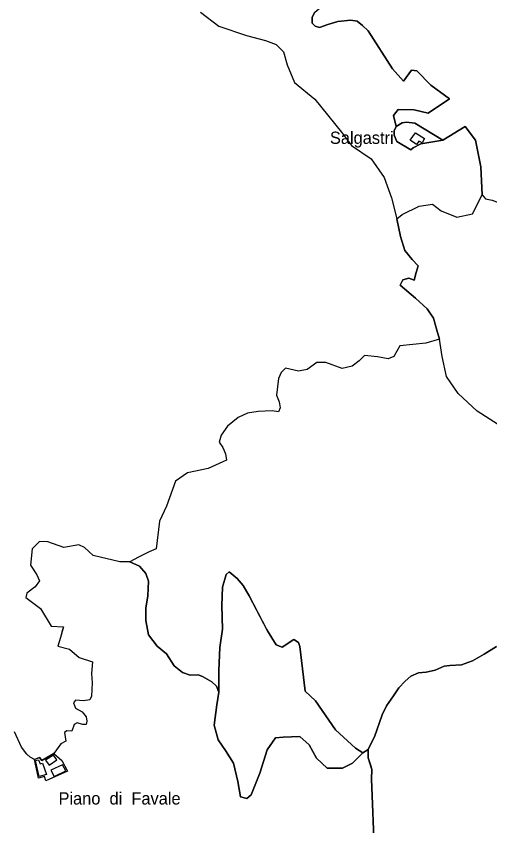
# Model space of a CAD drawing. Extents: x 645880 to 658994, y 884400 to 894744.
# Drawn here: x 655242 to 655899, y 892132 to 893255 of the extents above; entities that cross this region are included whole.
import ezdxf
from ezdxf.enums import TextEntityAlignment as Align

# ---------------------------------------------------------------- set-up
doc = ezdxf.new("R2010")
doc.units = 0
doc.header["$LTSCALE"] = 10
for name, color, linetype, lineweight in [('16', 7, 'Continuous', 25), ('17', 7, 'Continuous', 25), ('18', 7, 'Continuous', 25), ('4', 7, 'Continuous', 25)]:
    doc.layers.add(name, color=color, linetype=linetype, lineweight=lineweight)
doc.layers.add('60', color=7, linetype='Continuous')

msp = doc.modelspace()

# ---------------------------------------------------------------- linework, layer by layer
at = {"layer": '16'}
for points in [[(655652.59, 893245.87), (655652.9, 893254.21), (655656.27, 893260.95), (655673.25, 893274.81), (655677.27, 893286.81), (655672.13, 893296.24), (655662.77, 893302.78), (655661.99, 893309.77), (655670.76, 893325.78), (655674.38, 893335.22), (655673.89, 893349.59), (655656.98, 893368.6), (655634.51, 893389.65), (655626.13, 893385.49), (655607.9, 893382.51), (655593.91, 893399.81), (655585.33, 893424.33), (655583.16, 893438.12), (655583.47, 893454.87), (655594.74, 893465.4)], [(655497.71, 893261.19), (655523.09, 893241.6), (655561.51, 893228.53), (655588.19, 893221.64), (655602.74, 893216.24), (655612.98, 893206.04), (655618.05, 893187.89), (655628.2, 893163.22), (655656.35, 893140.23), (655693.22, 893094.49), (655707.43, 893075.95), (655734.54, 893057.47), (655752.43, 893031.48), (655762.74, 893003.47), (655769.96, 892974.46), (655777.68, 892980.49), (655801.34, 892991.77), (655819.4, 892994.83), (655831.69, 892985.31), (655853.49, 892976.46), (655875.14, 892981.46), (655888.55, 893007.47), (655886.49, 893046.49), (655879.27, 893083.5)], [(655662.77, 893239.64), (655656.86, 893241.52), (655652.59, 893245.87)], [(655730.58, 893235.17), (655722.66, 893242.51), (655714.96, 893248.35), (655706.21, 893249.85), (655688.18, 893248.26), (655674.37, 893243.99), (655662.77, 893239.64)], [(655879.27, 893083.5), (655864.69, 893102.53), (655833.82, 893083.57), (655803.46, 893078.52), (655792.86, 893072.99), (655789.63, 893070.22), (655770.26, 893081.76), (655766.58, 893090.52), (655766.58, 893096.52), (655769.34, 893102.52), (655765.35, 893117.58), (655772.03, 893126.17), (655793.99, 893125.7), (655813.56, 893120.92), (655843.28, 893140.94), (655817.19, 893159.62), (655797.97, 893179.45), (655790.64, 893180.44), (655779.55, 893165.41), (655764.26, 893182.3), (655730.58, 893235.17)], [(655829.33, 892807.49), (655810.29, 892801.7), (655774.43, 892798.33)], [(656246.73, 892704.86), (656219.92, 892710.37), (656199.3, 892713.37), (656162.69, 892717.37), (656141.04, 892717.37), (656125.57, 892716.37), (656121.36, 892719.13), (656121.12, 892718.66), (656104.57, 892695.85), (656075.19, 892664.84), (656044.38, 892632.77), (656026.62, 892616.45), (656007.72, 892614.56), (655991.84, 892616.22), (655982.38, 892619.71), (655921.47, 892682.13), (655881.54, 892707.33), (655855.43, 892732.01), (655839.07, 892755.46), (655833.01, 892783.59), (655829.33, 892807.49)], [(655774.43, 892798.33), (655766.1, 892783.46), (655757.98, 892780.28), (655743.16, 892783.04), (655725.28, 892784.65), (655717.86, 892777.36), (655708.44, 892770.17), (655694.18, 892766.93), (655671.49, 892774.93), (655659.12, 892774.93), (655645.82, 892765.21), (655633.73, 892763.23), (655615.9, 892767)], [(655615.9, 892767), (655609.95, 892761.25), (655605.91, 892752.7), (655603.47, 892729.73), (655607.01, 892720.72)], [(655607.01, 892720.72), (655608.37, 892712.07), (655606.23, 892706.52), (655597.25, 892707.91), (655577.66, 892706.91), (655563.22, 892704.9)], [(655563.22, 892704.9), (655550.3, 892698.78), (655535.38, 892686.9)], [(655535.38, 892686.9), (655526.32, 892674.39), (655523.54, 892664.68)], [(655523.54, 892664.68), (655528.69, 892657.34), (655532.65, 892648.22), (655533.84, 892639.5), (655508.35, 892628.05), (655479.97, 892622), (655463.29, 892610.35), (655450.61, 892575.65), (655441.09, 892554.83), (655436.55, 892516.76), (655426.64, 892512.59), (655411.78, 892505.06), (655399.88, 892498.36)], [(655399.88, 892498.36), (655385.88, 892498.36), (655349.06, 892507.48), (655336.89, 892518.38), (655329.35, 892522.07), (655308.36, 892518.29), (655286.28, 892526.37), (655274.44, 892526.91), (655264.21, 892516.68), (655262.18, 892493.74), (655270.7, 892480.65), (655274.66, 892472.33), (655268.68, 892463.93), (655256.83, 892455.07), (655255.84, 892449.13), (655275.9, 892433.92), (655290.92, 892409.47), (655307.96, 892408.48), (655306.66, 892404.1), (655303.61, 892393.8), (655300.24, 892381.51), (655316.29, 892377.54), (655329.56, 892365.85), (655348.08, 892359.9), (655346.61, 892343.64), (655347.6, 892330.75), (655346.61, 892312.11), (655344.63, 892307.34), (655335.47, 892305.7), (655324.42, 892306.75), (655321.65, 892302.98), (655324.62, 892295.64), (655333.93, 892290.29), (655339.09, 892283.55), (655340.27, 892277.4), (655339.48, 892272.84), (655334.53, 892272.84), (655329.83, 892274.43), (655326.74, 892275.43), (655322.61, 892272.93)], [(655399.88, 892498.36), (655413.34, 892492.44), (655421.95, 892482.2), (655425.72, 892471.97), (655424.65, 892451.49), (655421.95, 892434.26), (655421.95, 892417.02), (655425.66, 892397.27), (655437.8, 892381.55), (655450.65, 892370.83)], [(655421.95, 892417.02), (655421.95, 892434.26), (655424.65, 892451.49), (655425.72, 892471.97), (655421.95, 892482.2), (655413.34, 892492.44), (655399.88, 892498.36)], [(655450.65, 892370.83), (655461.34, 892354.31), (655472.95, 892345.28), (655483.52, 892341.41), (655494.87, 892341.67), (655500.54, 892339.61), (655513.43, 892332.12), (655520.14, 892326.19), (655523.53, 892317.96), (655523.46, 892347.69), (655524.46, 892379.77), (655528.47, 892405.04), (655527.47, 892438.09), (655528.47, 892463.37), (655533.48, 892480.87), (655537.49, 892484.75), (655548.95, 892475.27)], [(655548.95, 892475.27), (655557.13, 892465.95), (655565.32, 892451.26), (655589.56, 892405.18), (655589.56, 892405.17)], [(655520.14, 892326.19), (655513.43, 892332.12), (655500.54, 892339.61), (655494.87, 892341.67), (655483.52, 892341.41), (655472.95, 892345.28), (655461.34, 892354.31), (655450.65, 892370.83), (655437.8, 892381.55), (655425.66, 892397.27), (655421.95, 892417.02)], [(655589.56, 892405.17), (655590.72, 892402.96), (655602.65, 892383.23), (655611.36, 892380.32), (655627.13, 892390.81)], [(655627.13, 892390.81), (655633.75, 892386.84), (655635.64, 892380.99), (655642.99, 892319.23), (655657.33, 892305.63), (655685.32, 892265.64), (655713.01, 892239.91), (655723.02, 892233.7), (655730.45, 892238.34)], [(655730.45, 892238.34), (655734.91, 892247.88), (655739.14, 892256.07), (655749.82, 892286.41), (655756.02, 892298.82), (655765.32, 892312.78), (655773.03, 892323.59), (655781.59, 892332.94), (655789.34, 892339.91), (655800.19, 892344.57), (655810.9, 892345.51), (655823.43, 892348.44), (655835.83, 892353.87), (655843.58, 892354.65), (655859.71, 892355.72), (655875.3, 892361.11), (655891.08, 892370.39), (655908.34, 892380.98)], [(655590.43, 892238.02), (655580.26, 892205.54), (655568.13, 892175.6), (655561.92, 892170.24), (655553.17, 892172.5), (655549.51, 892194.09), (655543.85, 892219.1), (655532.48, 892236.86), (655522.46, 892251.45), (655517.04, 892272.2), (655520.45, 892300.05), (655523.53, 892317.95), (655520.14, 892326.19)], [(655322.61, 892272.93), (655319.52, 892263.92), (655312.73, 892264.11), (655309.21, 892261.92), (655310.24, 892255.92), (655311.27, 892249.92), (655304.05, 892245.92), (655294.4, 892232.82)], [(655294.4, 892232.82), (655305.47, 892223.02), (655313.52, 892207.99), (655283.61, 892194.75), (655281.64, 892201), (655273.09, 892198.37), (655267.64, 892224.38), (655261.8, 892227.43), (655256.91, 892231.7), (655249.68, 892241.57), (655239.83, 892262.62)], [(655738.97, 892092.57), (655735.1, 892197.24), (655735.55, 892210.32), (655730.45, 892226.71), (655730.45, 892231.59), (655730.45, 892238.34), (655723.02, 892233.7), (655708.84, 892219.37), (655694.81, 892212.56), (655673.77, 892212.56), (655658.74, 892226.17), (655648.47, 892244.63), (655635.69, 892256.31), (655612.64, 892255.33), (655601.72, 892254.4), (655590.43, 892238.02)]]:
    msp.add_lwpolyline(points, dxfattribs=at)
at = {"layer": '17'}
msp.add_lwpolyline([(655908.34, 892380.98), (655891.08, 892370.39), (655875.3, 892361.11), (655859.71, 892355.72), (655843.58, 892354.65), (655835.83, 892353.87), (655823.43, 892348.44), (655810.9, 892345.51), (655800.19, 892344.57), (655789.34, 892339.91), (655781.59, 892332.94), (655773.03, 892323.59), (655765.32, 892312.78), (655756.02, 892298.82), (655749.82, 892286.41), (655739.14, 892256.07), (655734.91, 892247.88), (655730.45, 892238.34), (655730.45, 892226.71), (655734.33, 892214.3), (655735.55, 892210.32), (655735.1, 892197.24), (655738.97, 892092.57)], dxfattribs=at)
at = {"layer": '18'}
for points in [[(655497.71, 893261.19), (655523.09, 893241.6), (655561.51, 893228.53), (655588.19, 893221.64), (655602.74, 893216.24), (655612.98, 893206.04), (655618.05, 893187.89), (655628.2, 893163.22), (655656.35, 893140.23), (655693.22, 893094.49), (655707.43, 893075.95), (655734.54, 893057.47), (655752.43, 893031.48), (655762.74, 893003.47), (655769.96, 892974.46)], [(655656.27, 893260.95), (655652.9, 893254.21), (655652.59, 893245.87)], [(655652.59, 893245.87), (655656.86, 893241.52), (655662.77, 893239.64), (655674.37, 893243.99), (655688.18, 893248.26), (655706.21, 893249.85), (655714.96, 893248.35)], [(655714.96, 893248.35), (655722.66, 893242.51), (655730.58, 893235.17), (655764.26, 893182.3), (655779.55, 893165.41), (655790.64, 893180.44), (655797.97, 893179.45), (655817.19, 893159.62), (655843.28, 893140.94), (655813.56, 893120.92)], [(655813.56, 893120.92), (655793.99, 893125.7), (655772.03, 893126.18), (655765.34, 893117.58), (655769.34, 893102.52), (655777.64, 893107.6), (655783.64, 893108.52), (655795.16, 893107.13), (655833.82, 893083.57), (655864.69, 893102.53), (655879.27, 893083.5), (655886.49, 893046.49), (655888.55, 893007.47)], [(655829.33, 892807.49), (655825.44, 892819.79), (655820.98, 892836.55), (655812.04, 892849.4), (655795.85, 892864.49), (655774.64, 892882.37), (655778.55, 892889.63), (655786.92, 892891.86), (655794.18, 892889.07), (655796.97, 892899.69), (655799.76, 892909.18), (655791.39, 892918.12), (655781.34, 892930.41), (655775.2, 892949.97), (655769.96, 892974.46), (655777.68, 892980.49), (655801.34, 892991.77), (655819.4, 892994.83), (655831.69, 892985.31), (655853.49, 892976.46), (655875.14, 892981.46), (655888.55, 893007.47)], [(655888.55, 893007.47), (655892.94, 893001.88), (655902.52, 893000.35)], [(655888.55, 893007.47), (655892.94, 893001.88), (655902.52, 893000.35), (655910.57, 892996.9), (655917.86, 892990.38), (655925.14, 892981.94), (655933.19, 892977.34), (655942, 892974.27), (655949.67, 892973.5), (655954.08, 892963.58), (655971.09, 893003.6)], [(655769.96, 892974.46), (655775.2, 892949.97), (655781.34, 892930.41), (655791.39, 892918.12), (655799.76, 892909.18), (655796.97, 892899.69), (655794.18, 892889.07), (655786.92, 892891.86), (655778.55, 892889.63), (655774.64, 892882.37), (655795.85, 892864.49), (655812.04, 892849.4), (655820.98, 892836.55), (655825.44, 892819.79), (655829.33, 892807.49)], [(655829.33, 892807.49), (655810.29, 892801.7), (655774.43, 892798.33)], [(655881.54, 892707.33), (655855.43, 892732.01), (655839.07, 892755.46), (655833.01, 892783.59), (655829.33, 892807.49)], [(655774.43, 892798.33), (655766.1, 892783.46), (655757.98, 892780.28), (655743.16, 892783.04), (655725.28, 892784.65), (655717.86, 892777.36), (655708.44, 892770.17), (655694.18, 892766.93), (655671.49, 892774.93), (655659.12, 892774.93), (655645.82, 892765.21), (655633.73, 892763.23), (655615.9, 892767)], [(655615.9, 892767), (655609.95, 892761.25), (655605.91, 892752.7), (655603.47, 892729.73), (655607.01, 892720.72)], [(655607.01, 892720.72), (655608.37, 892712.07), (655606.23, 892706.52), (655597.25, 892707.91), (655577.66, 892706.91), (655563.22, 892704.9)], [(655921.47, 892682.13), (655881.54, 892707.33)], [(655563.22, 892704.9), (655550.3, 892698.78), (655535.38, 892686.9)], [(655535.38, 892686.9), (655526.32, 892674.39), (655523.54, 892664.68)], [(655523.54, 892664.68), (655528.69, 892657.34), (655532.65, 892648.22), (655533.84, 892639.5), (655508.35, 892628.05), (655479.97, 892622), (655463.29, 892610.35), (655450.61, 892575.65), (655441.09, 892554.83), (655436.55, 892516.76), (655426.64, 892512.59), (655411.78, 892505.06), (655399.88, 892498.36), (655385.88, 892498.36), (655349.06, 892507.48), (655336.89, 892518.38), (655329.35, 892522.07), (655308.36, 892518.29), (655286.28, 892526.37), (655274.44, 892526.91), (655264.21, 892516.68), (655262.18, 892493.74), (655270.7, 892480.65), (655274.66, 892472.33), (655268.68, 892463.93), (655256.83, 892455.07), (655255.84, 892449.13), (655275.9, 892433.92), (655290.92, 892409.47), (655307.96, 892408.48), (655303.61, 892393.8), (655300.24, 892381.51), (655316.29, 892377.54), (655329.56, 892365.85), (655348.08, 892359.9), (655346.61, 892343.64), (655347.6, 892330.75), (655346.61, 892312.11), (655344.63, 892307.34), (655335.47, 892305.7)], [(655590.72, 892402.97), (655565.32, 892451.26), (655557.13, 892465.95), (655548.95, 892475.27), (655537.49, 892484.75), (655533.48, 892480.87)], [(655533.48, 892480.87), (655528.47, 892463.37), (655527.47, 892438.09), (655528.47, 892405.04), (655524.46, 892379.77), (655523.46, 892347.69), (655523.53, 892317.96), (655520.45, 892300.06), (655517.04, 892272.21), (655522.46, 892251.46), (655532.48, 892236.87), (655543.85, 892219.11), (655549.51, 892194.1), (655553.17, 892172.51), (655561.92, 892170.25), (655568.13, 892175.61), (655580.26, 892205.55), (655590.43, 892238.03), (655601.72, 892254.41), (655612.64, 892255.34), (655635.69, 892256.32), (655648.47, 892244.64), (655658.74, 892226.18), (655673.77, 892212.57), (655694.81, 892212.57), (655708.84, 892219.38), (655723.02, 892233.71), (655713.01, 892239.92), (655685.32, 892265.65), (655657.33, 892305.64), (655642.99, 892319.24), (655635.64, 892381)], [(655635.64, 892381), (655633.75, 892386.85), (655627.13, 892390.82), (655611.36, 892380.33), (655602.65, 892383.24), (655590.72, 892402.97)], [(655335.47, 892305.7), (655324.42, 892306.75), (655321.65, 892302.98), (655324.62, 892295.64), (655333.93, 892290.29), (655339.09, 892283.55), (655340.27, 892277.4), (655339.48, 892272.84), (655334.53, 892272.84), (655329.83, 892274.43), (655326.74, 892275.43), (655322.61, 892272.93), (655319.52, 892263.92), (655312.73, 892264.11), (655309.21, 892261.92), (655310.24, 892255.92), (655311.27, 892249.92), (655304.05, 892245.92), (655294.4, 892232.82), (655278.02, 892223.22), (655274.79, 892227.38), (655267.64, 892224.38), (655261.8, 892227.43), (655256.91, 892231.7), (655249.68, 892241.57), (655239.83, 892262.62)]]:
    msp.add_lwpolyline(points, dxfattribs=at)
at = {"layer": '4'}
for points in [[(655769.34, 893102.52), (655766.58, 893096.52), (655766.58, 893090.52), (655770.26, 893081.76), (655789.63, 893070.22), (655792.86, 893072.99), (655803.46, 893078.52), (655833.82, 893083.57), (655795.16, 893107.13), (655783.64, 893108.52), (655777.64, 893107.6)], [(655788.75, 893083.41), (655795.93, 893093.77), (655808.35, 893085.79), (655805.11, 893079.74), (655800.76, 893082.08), (655797.43, 893077.52)], [(655269.16, 892222.83), (655273.32, 892223.9), (655275.32, 892218.26), (655278.71, 892219.16), (655284.24, 892203.69), (655274.03, 892200.84)], [(655293.98, 892230.55), (655283.05, 892223.67), (655288.11, 892216.66), (655298.74, 892224.06)], [(655306.53, 892217.05), (655290.54, 892209.4), (655294.85, 892200.96), (655311.32, 892208.45)]]:
    msp.add_lwpolyline(points, close=True, dxfattribs=at)
for points in [[(655313.52, 892207.99), (655283.61, 892194.75), (655281.64, 892201), (655273.09, 892198.37), (655267.64, 892224.38), (655274.79, 892227.38), (655278.02, 892223.22), (655294.4, 892232.82)], [(655294.4, 892232.82), (655305.47, 892223.02), (655313.52, 892207.99)]]:
    msp.add_lwpolyline(points, dxfattribs=at)

# ---------------------------------------------------------------- texts
at = {"layer": '60'}
for s, p in [('Salgastri', (655721.57, 893078.28)), ('Piano  di  Favale', (655385.6, 892161.96))]:
    msp.add_text(s, height=17, dxfattribs=at).set_placement(p, align=Align.CENTER)

doc.saveas('drawing.dxf')
